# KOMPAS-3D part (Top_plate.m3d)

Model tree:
1. X Axis
2. Y Axis
3. Z Axis
4. Origin  (labels: D:\Program Files\ASCON\KOMPAS-3D V10\Sys\GRAPHIC_EN.LYT; Plate 04)
     Wall Thickness 1 = 1; Wall Thickness 2 = 1; Distance 1 = 10; Distance 2 = 10

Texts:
  Plate 04
  Three Point Plane
  Plane at Angle
  Line and Point Plane
  Axis through Two Vertices
  Axis of Feature
  Axis of Conical Surface
  Axis through Edge
  Trim by Surface
  Trim by Sketch
  Feature with No History
  Intersection Axis of Two Planes
  Two Line Plane
  Line and Face Plane
  Bend by line
  Hole in sheet body
  Cut in sheet body
  Point in CM
  Linear Dimension from Line to Point
  Surface Finish Symbol
  Geometric Tolerance Symbol
  Leader #1
  Leader #2
  Leader #3
  Shape Deviations and Datum
  Node point number
  Mark of coordination axis
  Node point designation
  Mark/Reference designation with leader
  Mark/reference designation on line
  Mark/Reference designation without leader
